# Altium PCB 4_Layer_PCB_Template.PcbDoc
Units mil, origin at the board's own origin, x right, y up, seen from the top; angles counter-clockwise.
Board outline 2000 x 2000 mil, 4 copper layers (Top Layer, Inner Layer 2, Inner Layer 3, Bottom Layer), stack 61.6 mil thick; 0 components, 0 nets, 0 pads, 3 vias.
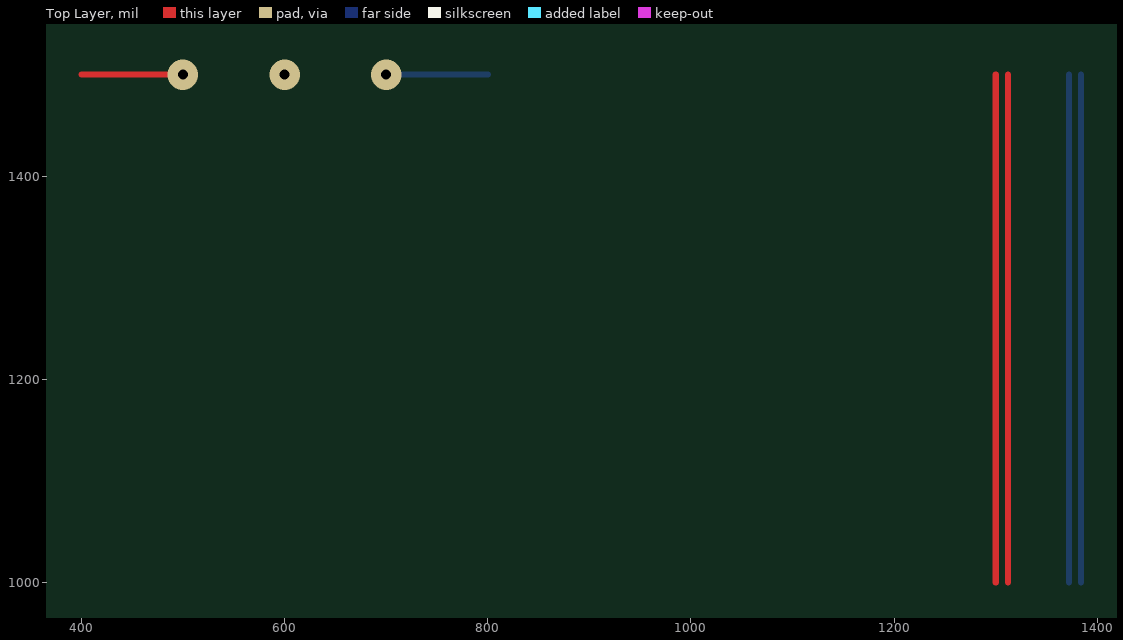
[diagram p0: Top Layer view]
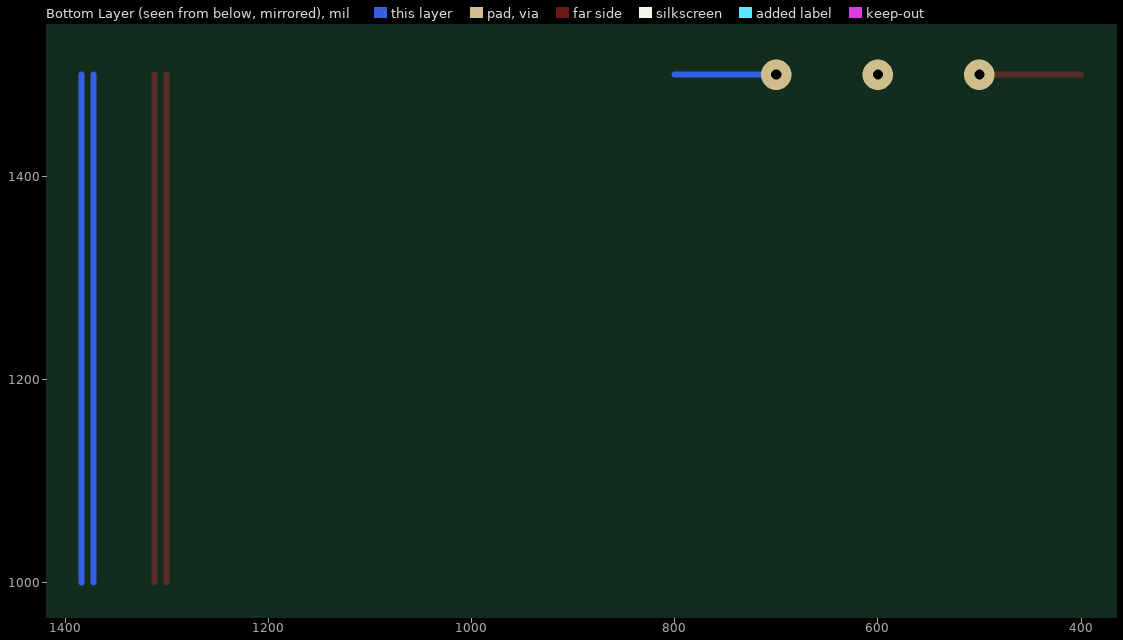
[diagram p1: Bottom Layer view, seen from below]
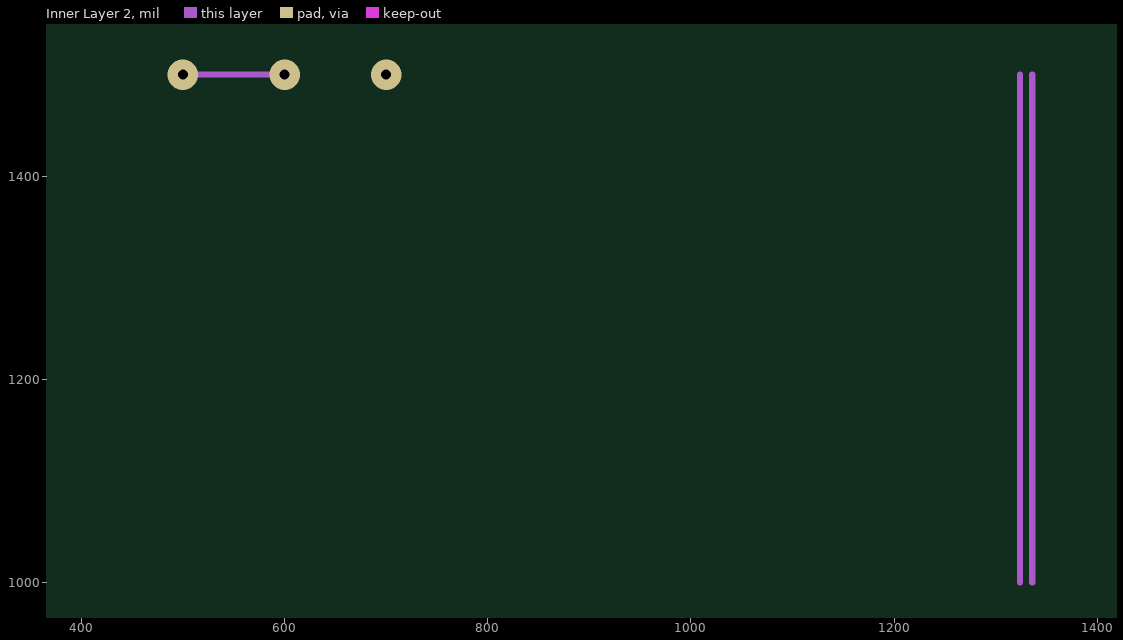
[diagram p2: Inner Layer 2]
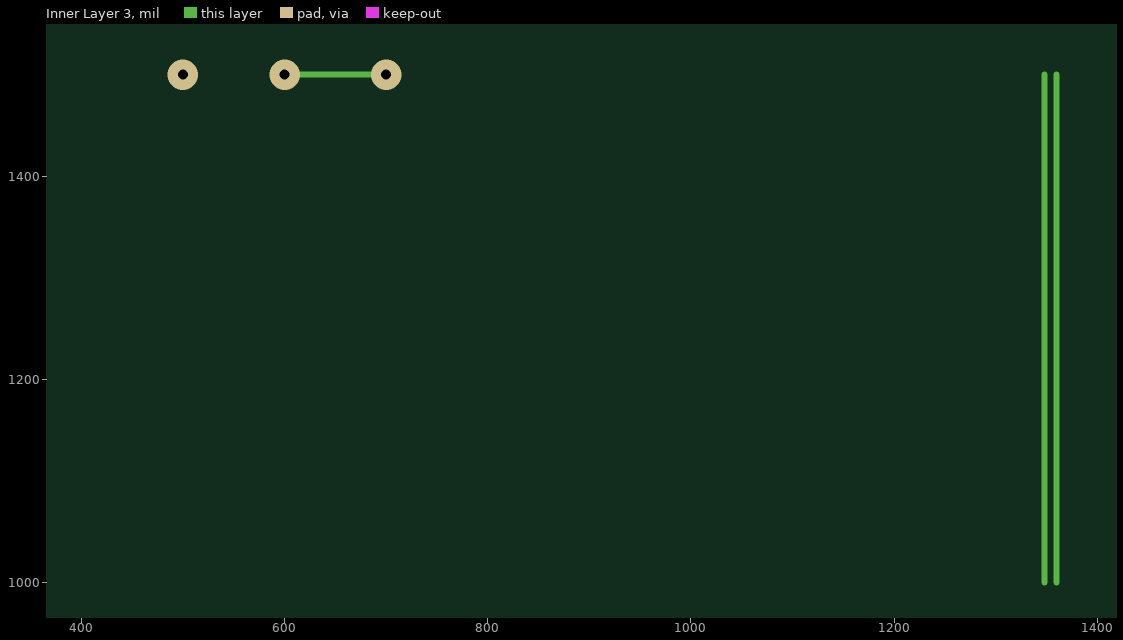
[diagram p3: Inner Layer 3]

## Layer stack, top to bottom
Top Solder: solder mask 0.4, Solder Resist, Dk 3.5
Top Layer: signal copper 1.4
Dielectric 1: core 25, 370HR, Dk 4.1
Inner Layer 2: signal copper 1.4
Dielectric 2: prepreg 6, 370HR, Dk 4.1
Inner Layer 3: signal copper 1.4
Dielectric 3: core 25, 370HR, Dk 4.1
Bottom Layer: signal copper 1.4
Bottom Solder: solder mask 0.4, Solder Resist, Dk 3.5

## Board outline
0,0 2000,0 2000,2000 0,2000

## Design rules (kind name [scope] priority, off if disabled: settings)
AcuteAngle [All] p1: minimum=6.00000000000000E+0001 checktracksonly=FALSE
BoardOutlineClearance [All] p1: gap=20 ignorepadtopadclearanceinfootprint=FALSE
Clearance [All] p1: gap=6 ignorepadtopadclearanceinfootprint=FALSE except(10: Arc-Poly Track-Poly SMDPad-Poly THPad-Poly Via-Poly Fill-Poly Poly-Poly Poly-Region Poly-Text Poly-Hole)
HoleSize [All] p1: absolutevalues=TRUE maxlimit=1000 minlimit=10 maxpercent=80.000 minpercent=20.000
HoleToHoleClearance [All] p1: gap=12 allowstackedmicrovias=TRUE
MinimumAnnularRing [All] p1: minimumring=10
MinimumSolderMaskSliver [All] p1: minsoldermaskwidth=3
PlaneClearance [All] p1: clearance=10
PlaneConnect [All] p1: planeconnectstyle=Relief reliefexpansion=10 reliefentries=4 reliefconductorwidth=10 reliefairgap=10
PolygonConnect [All] p1: connectstyle=Relief reliefconductorwidth=10 reliefentries=4 polygonreliefangle="90 Angle" airgapwidth=10
RoutingVias [All] p1: holewidth=28 width=50 viastyle="Through Hole" minholewidth=28 minwidth=50 maxholewidth=28 maxwidth=50
SilkToSilkClearance [All] p1: silktosilkclearance=0.1
SilkToSolderMaskClearance [IsPad] p1: minsilkscreentomaskgap=0.1 clearancetoexposedcopper=TRUE
SolderMaskExpansion [All] p1: expansion=2
Width [All] p1: maxlimit=1000 minlimit=6 preferedwidth=8
23 further rules are at their usual default settings.

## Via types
v1: diameter 30, hole 10, Top Layer to Bottom Layer, tented both sides, 3 vias

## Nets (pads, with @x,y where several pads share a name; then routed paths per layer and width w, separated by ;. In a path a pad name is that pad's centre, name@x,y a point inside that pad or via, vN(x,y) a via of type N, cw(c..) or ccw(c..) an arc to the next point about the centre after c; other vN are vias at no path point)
copper on no net: | length 4400
  Top Layer w6: 400,1500 v1(500,1500) ; 1300,1000 1300,1500 ; 1312,1000 1312,1500
  Inner Layer 2 w6: v1(500,1500) v1(600,1500) ; 1324,1000 1324,1500 ; 1336,1000 1336,1500
  Inner Layer 3 w6: v1(600,1500) v1(700,1500) ; 1348,1000 1348,1500 ; 1360,1000 1360,1500
  Bottom Layer w6: v1(700,1500) 800,1500 ; 1372,1000 1372,1500 ; 1384,1000 1384,1500

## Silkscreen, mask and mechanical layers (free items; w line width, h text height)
BOARD_OUTLINE:
  the board outline again, w10
DESIGN_NOTES:
  region: 1300,1520 1280,1570 1300,1560 1320,1570
  region: 500,1520 480,1570 500,1560 520,1570
  lines w3.94: -178.74,0 -21.26,0 ; -178.74,1000 -21.26,1000 ; -120,60 -100,0 ; -120,940 -100,1000 ; -100,224.08 -100,0 ; -100,775.92 -100,1000 ; -80,60 -100,0 ; -80,940 -100,1000 ; 0,-178.74 0,-21.26 ; 0,5821.26 0,5978.74 ; 60,-120 0,-100 ; 60,-80 0,-100 ; 60,5880 0,5900 ; 60,5920 0,5900 ; 224.08,-100 0,-100 ; 775.92,-100 1000,-100 ; 940,-120 1000,-100 ; 940,-80 1000,-100 ; 1000,-178.74 1000,-21.26 ; 2719.09,5900 0,5900 ; 3280.91,5900 6000,5900 ; 5821.26,0 5978.74,0 ; 5821.26,6000 5978.74,6000 ; 5880,60 5900,0 ; 5880,5940 5900,6000 ; 5900,2719.09 5900,0 ; 5900,3280.91 5900,6000 ; 5920,60 5900,0 ; 5920,5940 5900,6000 ; 5940,5880 6000,5900 ; 5940,5920 6000,5900 ; 6000,5821.26 6000,5978.74
  lines w10: 0,1000 1000,1000 1000,0 ; 500,1550 500,1630 ; 1300,1550 1300,1630 ; 0,0 6000,0 6000,6000 0,6000 0,0
  text "Maximum Board Size" at 4200,6100 h200
  text "6000 (mil)" at 2729.09,5864.01 h60
  text "6000 (mil)" at 5935.99,2729.09 h60 r90
  text "Smallest Via" at 450,1650 h100
  text "6/6 (mil) Trace/Space" at 1210,1630 h100
  text "Minimum Board Size" at 60,500 h100
  text "1000 (mil)" at -64.01,234.08 h60 r90
  text "1000 (mil)" at 234.08,-135.99 h60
